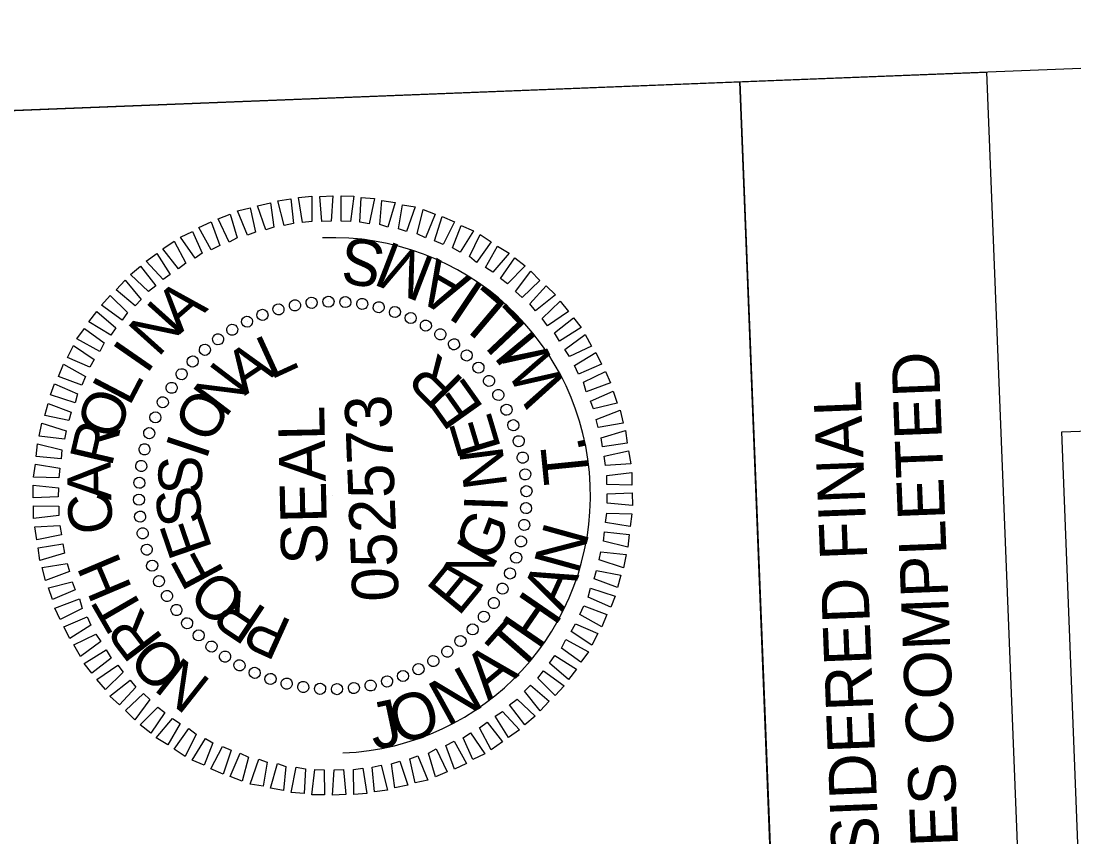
# Model space of a CAD drawing. Extents: x 1627905 to 1629071, y 761064 to 763101.
# Drawn here: x 1627988 to 1628124.3, y 762759.2 to 762864.8 of the extents above; entities that cross this region are included whole.
import ezdxf

# ---------------------------------------------------------------- set-up
doc = ezdxf.new("R2010")
doc.units = 0
for name, color, linetype in [('Prop DSN Text', 7, 'Continuous'), ('Scratch_Level_0', 7, 'Continuous'), ('Sheet Clip Boundary CELL', 7, 'Continuous'), ('Sheet Plan And Profile CELL', 7, 'Continuous'), ('Sheet Professional Seal CELL', 7, 'Continuous'), ('Sheet Profile Grid Minor CELL', 7, 'Continuous'), ('Sheet Sticker Exception Certification CELL', 7, 'Continuous')]:
    doc.layers.add(name, color=color, linetype=linetype)

msp = doc.modelspace()

# ---------------------------------------------------------------- linework, layer by layer
at = {"layer": 'Scratch_Level_0'}
msp.add_arc((1628028.37, 762803.44), 33.36, 272.2582, 92.2582, dxfattribs=at)
at = {"layer": 'Sheet Clip Boundary CELL'}
msp.add_lwpolyline([(1628129.05, 762651.6), (1628122.74, 762811.67), (1628982.18, 762845.56), (1629039.43, 761393.61), (1627990.25, 761352.23), (1627946.91, 762451.28), (1628013.55, 762453.91), (1628005.94, 762646.74)], close=True, dxfattribs=at)
at = {"layer": 'Sheet Plan And Profile CELL'}
for points in [[(1627931.14, 762851.07), (1627990.25, 761352.23), (1629039.43, 761393.61), (1628980.33, 762892.44)], [(1627972.6, 762752.63), (1627968.66, 762852.55), (1628081.08, 762856.98), (1628085.02, 762757.06)]]:
    msp.add_lwpolyline(points, close=True, dxfattribs=at)
at = {"layer": 'Sheet Professional Seal CELL'}
for p, q in [((1628021.32, 762827.53), (1628021.32, 762827.53)), ((1628023.5, 762828.02), (1628023.5, 762828.02)), ((1628025.64, 762828.4), (1628025.64, 762828.4)), ((1628027.83, 762828.54), (1628027.83, 762828.54)), ((1628030.04, 762828.47), (1628030.04, 762828.47)), ((1628032.2, 762828.21), (1628032.2, 762828.21)), ((1628034.32, 762827.84), (1628034.32, 762827.84)), ((1628019.24, 762826.85), (1628019.24, 762826.85)), ((1628036.44, 762827.23), (1628036.44, 762827.23)), ((1628038.48, 762826.4), (1628038.48, 762826.4)), ((1628015.37, 762824.89), (1628015.37, 762824.89)), ((1628017.28, 762825.97), (1628017.28, 762825.97)), ((1628040.46, 762825.48), (1628040.46, 762825.48)), ((1628013.52, 762823.67), (1628013.52, 762823.67)), ((1628042.31, 762824.3), (1628042.31, 762824.3)), ((1628011.82, 762822.35), (1628011.82, 762822.35)), ((1628044.11, 762823.02), (1628044.11, 762823.02)), ((1628010.23, 762820.79), (1628010.23, 762820.79)), ((1628045.72, 762821.59), (1628045.72, 762821.59)), ((1628047.29, 762820), (1628047.29, 762820)), ((1628008.79, 762819.18), (1628008.79, 762819.18)), ((1628048.6, 762818.3), (1628048.6, 762818.3)), ((1628007.51, 762817.38), (1628007.51, 762817.38)), ((1628006.33, 762815.53), (1628006.33, 762815.53)), ((1628049.83, 762816.44), (1628049.83, 762816.44)), ((1628050.9, 762814.54), (1628050.9, 762814.54)), ((1628005.41, 762813.54), (1628005.41, 762813.54)), ((1628051.78, 762812.57), (1628051.78, 762812.57)), ((1628004.59, 762811.51), (1628004.59, 762811.51)), ((1628052.46, 762810.49), (1628052.46, 762810.49)), ((1628003.97, 762809.38), (1628003.97, 762809.38)), ((1628052.95, 762808.31), (1628052.95, 762808.31)), ((1628003.6, 762807.27), (1628003.6, 762807.27)), ((1628053.34, 762806.17), (1628053.34, 762806.17)), ((1628003.34, 762805.1), (1628003.34, 762805.1)), ((1628003.28, 762802.9), (1628003.28, 762802.9)), ((1628028.37, 762803.44), (1628028.37, 762803.44)), ((1628053.47, 762803.98), (1628053.47, 762803.98)), ((1628053.41, 762801.77), (1628053.41, 762801.77)), ((1628003.41, 762800.7), (1628003.41, 762800.7)), ((1628053.14, 762799.61), (1628053.14, 762799.61)), ((1628003.8, 762798.57), (1628003.8, 762798.57)), ((1628052.78, 762797.5), (1628052.78, 762797.5)), ((1628004.28, 762796.38), (1628004.28, 762796.38)), ((1628052.16, 762795.37), (1628052.16, 762795.37)), ((1628004.97, 762794.31), (1628004.97, 762794.31)), ((1628051.34, 762793.34), (1628051.34, 762793.34)), ((1628005.84, 762792.34), (1628005.84, 762792.34)), ((1628050.42, 762791.35), (1628050.42, 762791.35)), ((1628006.92, 762790.43), (1628006.92, 762790.43)), ((1628049.24, 762789.5), (1628049.24, 762789.5)), ((1628008.14, 762788.58), (1628008.14, 762788.58)), ((1628009.46, 762786.88), (1628009.46, 762786.88)), ((1628047.96, 762787.7), (1628047.96, 762787.7)), ((1628011.03, 762785.29), (1628011.03, 762785.29)), ((1628046.52, 762786.09), (1628046.52, 762786.09)), ((1628012.63, 762783.85), (1628012.63, 762783.85)), ((1628044.93, 762784.53), (1628044.93, 762784.53)), ((1628014.44, 762782.57), (1628014.44, 762782.57)), ((1628043.23, 762783.21), (1628043.23, 762783.21)), ((1628016.28, 762781.4), (1628016.28, 762781.4)), ((1628041.38, 762781.98), (1628041.38, 762781.98)), ((1628018.27, 762780.47), (1628018.27, 762780.47)), ((1628037.5, 762780.03), (1628037.5, 762780.03)), ((1628039.47, 762780.91), (1628039.47, 762780.91)), ((1628020.3, 762779.65), (1628020.3, 762779.65)), ((1628022.43, 762779.04), (1628022.43, 762779.04)), ((1628024.55, 762778.67), (1628024.55, 762778.67)), ((1628026.71, 762778.4), (1628026.71, 762778.4)), ((1628028.91, 762778.34), (1628028.91, 762778.34)), ((1628031.11, 762778.48), (1628031.11, 762778.48)), ((1628033.25, 762778.86), (1628033.25, 762778.86)), ((1628035.43, 762779.35), (1628035.43, 762779.35))]:
    msp.add_line(p, q, dxfattribs=at)
for points in [[(1628019.71, 762837.82), (1628018.64, 762840.93), (1628020.33, 762841.3), (1628020.75, 762838.17)], [(1628022.09, 762838.37), (1628021.27, 762841.59), (1628022.96, 762841.81), (1628023.28, 762838.62)], [(1628024.48, 762838.76), (1628023.95, 762841.99), (1628025.65, 762842.16), (1628025.67, 762838.91)], [(1628026.98, 762838.91), (1628026.7, 762842.15), (1628028.4, 762842.22), (1628028.17, 762838.96)], [(1628029.48, 762838.96), (1628029.45, 762842.21), (1628031.1, 762842.18), (1628030.68, 762838.91)], [(1628031.88, 762838.8), (1628032.06, 762842.01), (1628033.76, 762841.88), (1628033.09, 762838.6)], [(1628034.45, 762838.51), (1628034.72, 762841.62), (1628036.44, 762841.34), (1628035.51, 762838.15)], [(1628036.87, 762837.95), (1628037.4, 762841.07), (1628039.06, 762840.79), (1628037.94, 762837.59)], [(1628014.97, 762836.24), (1628013.55, 762839.23), (1628015.08, 762839.84), (1628016, 762836.78)], [(1628017.34, 762837.13), (1628016.06, 762840.28), (1628017.7, 762840.65), (1628018.37, 762837.52)], [(1628039.3, 762837.3), (1628040.08, 762840.43), (1628041.65, 762839.84), (1628040.37, 762836.79)], [(1628012.66, 762835.24), (1628011.04, 762838.13), (1628012.62, 762838.85), (1628013.74, 762835.79)], [(1628041.54, 762836.38), (1628042.56, 762839.53), (1628044.14, 762838.84), (1628042.65, 762835.93)], [(1628043.87, 762835.47), (1628045.01, 762838.37), (1628046.59, 762837.68), (1628044.85, 762834.91)], [(1628010.55, 762834.16), (1628008.69, 762836.89), (1628010.21, 762837.6), (1628011.48, 762834.8)], [(1628046.07, 762834.36), (1628047.46, 762837.22), (1628048.9, 762836.27), (1628047, 762833.6)], [(1628008.4, 762832.77), (1628006.4, 762835.35), (1628007.86, 762836.36), (1628009.37, 762833.51)], [(1628048.13, 762832.94), (1628049.72, 762835.71), (1628051.21, 762834.81), (1628049.1, 762832.33)], [(1628006.41, 762831.4), (1628004.21, 762833.76), (1628005.62, 762834.77), (1628007.33, 762832.03)], [(1628050.08, 762831.52), (1628051.93, 762834.19), (1628053.27, 762833.14), (1628051.01, 762830.85)], [(1628004.52, 762829.82), (1628002.18, 762832.03), (1628003.48, 762833.13), (1628005.49, 762830.56)], [(1628052.05, 762829.84), (1628054, 762832.47), (1628055.2, 762831.27), (1628052.88, 762829.07)], [(1628002.79, 762828), (1628000.35, 762830.06), (1628001.51, 762831.3), (1628003.56, 762828.78)], [(1628053.87, 762828.26), (1628055.98, 762830.55), (1628057.22, 762829.4), (1628054.6, 762827.34)], [(1628001.11, 762826.13), (1627998.43, 762828.08), (1627999.58, 762829.32), (1628001.82, 762827.11)], [(1628055.49, 762826.33), (1628057.81, 762828.57), (1628058.91, 762827.26), (1628056.18, 762825.4)], [(1627999.63, 762824.17), (1627996.81, 762825.91), (1627997.86, 762827.26), (1628000.3, 762825.15)], [(1628057.07, 762824.49), (1628059.54, 762826.43), (1628060.54, 762825.17), (1628057.71, 762823.41)], [(1627998.22, 762822.07), (1627995.25, 762823.7), (1627996.25, 762825.04), (1627998.77, 762823.19)], [(1628058.4, 762822.34), (1628061.03, 762824.29), (1628061.89, 762822.77), (1628059.04, 762821.41)], [(1627996.94, 762820.06), (1627994.04, 762821.3), (1627994.83, 762822.83), (1627997.51, 762821.04)], [(1628059.69, 762820.24), (1628062.42, 762821.94), (1628063.18, 762820.42), (1628060.18, 762819.15)], [(1627995.89, 762817.72), (1627992.89, 762818.85), (1627993.53, 762820.43), (1627996.39, 762818.84)], [(1628060.82, 762818.08), (1628063.67, 762819.49), (1628064.33, 762818.02), (1628061.17, 762816.84)], [(1627995.03, 762815.43), (1627991.83, 762816.46), (1627992.38, 762817.88), (1627995.33, 762816.6)], [(1628061.72, 762815.66), (1628064.67, 762816.93), (1628065.18, 762815.4), (1628062.11, 762814.63)], [(1627994.21, 762813.15), (1627991.09, 762813.78), (1627991.53, 762815.35), (1627994.52, 762814.21)], [(1628062.46, 762813.29), (1628065.57, 762814.46), (1628065.99, 762812.78), (1628062.75, 762812.25)], [(1627993.66, 762810.73), (1627990.39, 762811.1), (1627990.73, 762812.81), (1627993.87, 762811.79)], [(1628063.11, 762810.91), (1628066.27, 762811.84), (1628066.49, 762810.2), (1628063.3, 762809.72)], [(1627993.21, 762808.16), (1627990, 762808.48), (1627990.18, 762810.14), (1627993.31, 762809.36)], [(1628063.5, 762808.53), (1628066.68, 762809.2), (1628066.94, 762807.51), (1628063.7, 762807.33)], [(1627992.91, 762805.74), (1627989.65, 762805.82), (1627989.88, 762807.48), (1627993.06, 762806.95)], [(1628063.85, 762806.04), (1628067.09, 762806.42), (1628067.1, 762804.77), (1628063.85, 762804.84)], [(1627992.85, 762803.24), (1627989.61, 762803.11), (1627989.59, 762804.76), (1627992.86, 762804.44)], [(1628063.89, 762803.64), (1628067.14, 762803.77), (1628067.16, 762802.12), (1628063.89, 762802.44)], [(1627992.9, 762800.84), (1627989.66, 762800.46), (1627989.65, 762802.11), (1627992.9, 762802.04)], [(1628063.84, 762801.13), (1628067.1, 762801.06), (1628066.86, 762799.4), (1628063.69, 762799.93)], [(1627993.25, 762798.35), (1627990.07, 762797.68), (1627989.8, 762799.37), (1627993.05, 762799.54)], [(1628063.54, 762798.72), (1628066.75, 762798.4), (1628066.57, 762796.74), (1628063.43, 762797.52)], [(1627993.64, 762795.96), (1627990.48, 762795.04), (1627990.26, 762796.68), (1627993.44, 762797.16)], [(1628063.09, 762796.15), (1628066.36, 762795.78), (1628066.02, 762794.07), (1628062.88, 762795.09)], [(1627994.29, 762793.59), (1627991.18, 762792.41), (1627990.76, 762794.1), (1627993.99, 762794.63)], [(1628062.53, 762793.73), (1628065.66, 762793.1), (1628065.22, 762791.53), (1628062.22, 762792.66)], [(1627995.03, 762791.22), (1627992.08, 762789.95), (1627991.57, 762791.48), (1627994.64, 762792.25)], [(1628061.72, 762791.44), (1628064.92, 762790.42), (1628064.37, 762789), (1628061.42, 762790.28)], [(1627995.93, 762788.8), (1627993.08, 762787.39), (1627992.42, 762788.86), (1627995.58, 762790.04)], [(1628060.86, 762789.16), (1628063.86, 762788.03), (1628063.22, 762786.45), (1628060.36, 762788.04)], [(1627997.06, 762786.64), (1627994.33, 762784.93), (1627993.57, 762786.45), (1627996.57, 762787.72)], [(1628059.8, 762786.81), (1628062.7, 762785.58), (1628061.91, 762784.05), (1628059.24, 762785.84)], [(1627998.35, 762784.54), (1627995.72, 762782.59), (1627994.86, 762784.1), (1627997.71, 762785.47)], [(1628058.53, 762784.81), (1628061.5, 762783.18), (1628060.5, 762781.84), (1628057.98, 762783.69)], [(1627999.68, 762782.39), (1627997.21, 762780.44), (1627996.21, 762781.7), (1627999.04, 762783.47)], [(1628057.11, 762782.71), (1628059.93, 762780.97), (1628058.89, 762779.62), (1628056.45, 762781.73)], [(1628001.25, 762780.55), (1627998.94, 762778.31), (1627997.84, 762779.62), (1628000.57, 762781.48)], [(1628055.64, 762780.75), (1628058.32, 762778.8), (1628057.17, 762777.55), (1628054.93, 762779.77)], [(1628002.88, 762778.62), (1628000.77, 762776.33), (1627999.52, 762777.48), (1628002.15, 762779.54)], [(1628053.96, 762778.88), (1628056.39, 762776.82), (1628055.24, 762775.58), (1628053.19, 762778.1)], [(1628004.7, 762777.04), (1628002.75, 762774.41), (1628001.55, 762775.61), (1628003.86, 762777.8)], [(1628052.23, 762777.06), (1628054.57, 762774.85), (1628053.26, 762773.75), (1628051.26, 762776.32)], [(1628006.66, 762775.36), (1628004.82, 762772.69), (1628003.47, 762773.73), (1628005.74, 762776.03)], [(1628008.62, 762773.94), (1628007.03, 762771.17), (1628005.54, 762772.07), (1628007.65, 762774.55)], [(1628050.34, 762775.48), (1628052.54, 762773.12), (1628051.13, 762772.11), (1628049.42, 762774.85)], [(1628010.68, 762772.52), (1628009.29, 762769.66), (1628007.85, 762770.6), (1628009.75, 762773.28)], [(1628048.35, 762774.1), (1628050.35, 762771.53), (1628048.89, 762770.52), (1628047.37, 762773.36)], [(1628012.87, 762771.4), (1628011.74, 762768.51), (1628010.16, 762769.19), (1628011.9, 762771.97)], [(1628044.09, 762771.63), (1628045.7, 762768.74), (1628044.13, 762768.03), (1628043.01, 762771.09)], [(1628046.2, 762772.72), (1628048.06, 762769.99), (1628046.53, 762769.28), (1628045.27, 762772.08)], [(1628015.21, 762770.49), (1628014.18, 762767.35), (1628012.61, 762768.04), (1628014.09, 762770.95)], [(1628041.78, 762770.64), (1628043.2, 762767.65), (1628041.67, 762767.03), (1628040.75, 762770.1)], [(1628017.45, 762769.58), (1628016.67, 762766.45), (1628015.1, 762767.04), (1628016.38, 762770.09)], [(1628019.88, 762768.93), (1628019.35, 762765.8), (1628017.69, 762766.09), (1628018.81, 762769.29)], [(1628037.04, 762769.05), (1628038.11, 762765.94), (1628036.42, 762765.58), (1628036, 762768.71)], [(1628039.41, 762769.75), (1628040.69, 762766.6), (1628039.05, 762766.23), (1628038.37, 762769.36)], [(1628022.3, 762768.37), (1628022.02, 762765.26), (1628020.31, 762765.54), (1628021.24, 762768.73)], [(1628024.86, 762768.07), (1628024.69, 762764.86), (1628022.98, 762765), (1628023.66, 762768.28)], [(1628027.27, 762767.92), (1628027.3, 762764.67), (1628025.65, 762764.7), (1628026.07, 762767.97)], [(1628029.77, 762767.97), (1628030.05, 762764.73), (1628028.35, 762764.66), (1628028.57, 762767.92)], [(1628032.27, 762768.12), (1628032.8, 762764.88), (1628031.1, 762764.72), (1628031.07, 762767.97)], [(1628034.66, 762768.51), (1628035.48, 762765.29), (1628033.79, 762765.07), (1628033.46, 762768.26)]]:
    msp.add_lwpolyline(points, close=True, dxfattribs=at)
for centre, major_axis in [((1628023.48, 762828.04), (-0.141, 0.706)), ((1628025.64, 762828.37), (-0.078, 0.716)), ((1628027.82, 762828.51), (-0.016, 0.72)), ((1628030.01, 762828.47), (0.047, 0.718)), ((1628032.19, 762828.23), (0.109, 0.712)), ((1628019.28, 762826.81), (-0.261, 0.671)), ((1628021.35, 762827.52), (-0.202, 0.691)), ((1628034.33, 762827.8), (0.171, 0.699)), ((1628036.43, 762827.19), (0.231, 0.682)), ((1628017.28, 762825.93), (-0.319, 0.646)), ((1628038.47, 762826.4), (0.29, 0.659)), ((1628040.43, 762825.43), (0.346, 0.631)), ((1628015.36, 762824.88), (-0.374, 0.615)), ((1628042.3, 762824.29), (0.4, 0.599)), ((1628013.54, 762823.66), (-0.426, 0.581)), ((1628044.07, 762823), (0.451, 0.562)), ((1628011.83, 762822.29), (-0.475, 0.541)), ((1628045.71, 762821.56), (0.498, 0.52)), ((1628010.25, 762820.78), (-0.52, 0.498)), ((1628047.23, 762819.98), (0.541, 0.475)), ((1628008.81, 762819.13), (-0.562, 0.451)), ((1628007.52, 762817.37), (-0.599, 0.4)), ((1628048.6, 762818.27), (0.581, 0.426)), ((1628049.81, 762816.45), (0.615, 0.374)), ((1628006.38, 762815.5), (-0.631, 0.346)), ((1628050.87, 762814.53), (0.646, 0.319)), ((1628005.42, 762813.54), (-0.659, 0.29)), ((1628051.75, 762812.53), (0.671, 0.261)), ((1628004.62, 762811.5), (-0.682, 0.231)), ((1628052.45, 762810.46), (0.691, 0.202)), ((1628004.01, 762809.4), (-0.699, 0.171)), ((1628052.97, 762808.34), (0.706, 0.141)), ((1628003.59, 762807.25), (-0.712, 0.109)), ((1628053.3, 762806.17), (0.716, 0.078)), ((1628003.35, 762805.08), (-0.718, 0.047)), ((1628053.45, 762803.99), (0.72, 0.016)), ((1628003.3, 762802.89), (-0.72, -0.016)), ((1628053.4, 762801.8), (0.718, -0.047)), ((1628003.44, 762800.71), (-0.716, -0.078)), ((1628053.16, 762799.63), (0.712, -0.109)), ((1628003.78, 762798.54), (-0.706, -0.141)), ((1628052.74, 762797.48), (0.699, -0.171)), ((1628004.3, 762796.42), (-0.691, -0.202)), ((1628052.12, 762795.38), (0.682, -0.231)), ((1628005, 762794.35), (-0.671, -0.261)), ((1628051.33, 762793.34), (0.659, -0.29)), ((1628005.88, 762792.34), (-0.646, -0.319)), ((1628050.36, 762791.38), (0.631, -0.346)), ((1628006.93, 762790.43), (-0.615, -0.374)), ((1628008.15, 762788.61), (-0.581, -0.426)), ((1628049.23, 762789.51), (0.599, -0.4)), ((1628047.94, 762787.74), (0.562, -0.451)), ((1628009.52, 762786.9), (-0.541, -0.475)), ((1628046.49, 762786.1), (0.52, -0.498)), ((1628011.03, 762785.32), (-0.498, -0.52)), ((1628044.91, 762784.59), (0.475, -0.541)), ((1628012.68, 762783.88), (-0.451, -0.562)), ((1628043.21, 762783.22), (0.426, -0.581)), ((1628014.44, 762782.58), (-0.4, -0.599)), ((1628041.39, 762782), (0.374, -0.615)), ((1628016.31, 762781.45), (-0.346, -0.631)), ((1628018.28, 762780.48), (-0.29, -0.659)), ((1628039.47, 762780.95), (0.319, -0.646)), ((1628020.32, 762779.69), (-0.231, -0.682)), ((1628022.42, 762779.08), (-0.171, -0.699)), ((1628035.4, 762779.36), (0.202, -0.691)), ((1628037.47, 762780.07), (0.261, -0.671)), ((1628024.56, 762778.65), (-0.109, -0.712)), ((1628026.74, 762778.41), (-0.047, -0.718)), ((1628028.92, 762778.37), (0.016, -0.72)), ((1628031.11, 762778.51), (0.078, -0.716)), ((1628033.27, 762778.84), (0.141, -0.706))]:
    msp.add_ellipse(centre, major_axis=major_axis, ratio=0.999708, dxfattribs=at)
at = {"layer": 'Sheet Sticker Exception Certification CELL'}
for p, q in [((1628081.08, 762856.98), (1628113.03, 762858.24)), ((1628113.01, 762858.24), (1628120.9, 762658.35)), ((1628088.94, 762657.09), (1628081.06, 762856.98))]:
    msp.add_line(p, q, dxfattribs=at)

# ---------------------------------------------------------------- texts
at = {"layer": 'Prop DSN Text'}
for s, rotation, p in [('S', 170.5234, (1628035.39, 762836.09)), ('M', 158.8769, (1628041.84, 762834)), ('A', 149.947, (1628046.42, 762831.54)), ('I', 146.1065, (1628048.26, 762830.27)), ('L', 139.7681, (1628051.1, 762827.91)), ('L', 133.4297, (1628053.67, 762825.25)), ('I', 129.5892, (1628055.07, 762823.51)), ('W', 116.928, (1628058.82, 762817.17)), ('.', 102.5495, (1628061.28, 762809.18)), ('T', 95.6803, (1628061.73, 762805.2)), ('N', 74.5419, (1628060.12, 762793.06)), ('A', 65.6119, (1628058.12, 762788.25)), ('H', 55.5267, (1628055, 762783.28)), ('T', 48.6575, (1628052.4, 762780.24)), ('A', 39.7275, (1628048.51, 762776.79)), ('N', 28.8929, (1628043.14, 762773.48)), ('J', 11.9042, (1628033.74, 762770.47)), ('O', 17.2153, (1628036.77, 762771.11))]:
    msp.add_text(s, height=6, rotation=rotation, dxfattribs=at).set_placement(p)
at = {"layer": 'Sheet Professional Seal CELL'}
for s, height, rotation, p in [('A', 5.64, 40.8753, (1628008.59, 762824.28)), ('N', 5.64, 48.0771, (1628005.76, 762821.21)), ('I', 5.64, 55.2783, (1628004.29, 762819)), ('L', 5.64, 24.659, (1628020.33, 762818.38)), ('A', 5.64, 34.0185, (1628016.96, 762816.3)), ('N', 5.64, 52.7348, (1628014.47, 762813.35)), ('R', 5.64, 134.7396, (1628045.55, 762818.23)), ('L', 5.64, 62.4791, (1628002.05, 762814.86)), ('E', 5.64, 125.3823, (1628048.04, 762814.77)), ('O', 5.64, 69.6794, (1628000.38, 762810.39)), ('O', 5.64, 62.0917, (1628012.61, 762809.92)), ('SEAL', 5.998, 91.2582, (1628027.72, 762794.56)), ('E', 5.64, 106.67, (1628050.2, 762809.55)), ('R', 5.64, 76.8793, (1627999.76, 762807.01)), ('I', 5.64, 71.4478, (1628011.99, 762807.9)), ('N', 5.64, 97.3146, (1628050.99, 762804.63)), ('A', 5.64, 91.2785, (1627999.73, 762802.81)), ('S', 5.64, 90.1586, (1628011.46, 762803.57)), ('S', 5.64, 99.5138, (1628011.65, 762799.98)), ('C', 5.64, 98.4781, (1628000.18, 762798.87)), ('I', 5.64, 87.9594, (1628050.98, 762801.28)), ('E', 5.64, 108.8693, (1628012.83, 762796.57)), ('G', 5.64, 69.2484, (1628049.34, 762794.66)), ('N', 5.64, 59.8921, (1628047.24, 762790.77)), ('F', 5.64, 118.2252, (1628014.46, 762793.43)), ('H', 5.64, 112.8777, (1628002.48, 762791.36)), ('E', 5.64, 50.5351, (1628044.66, 762787.67)), ('O', 5.64, 136.9394, (1628017.54, 762790.25)), ('R', 5.64, 146.2978, (1628020.05, 762788.6)), ('T', 5.64, 120.078, (1628004.26, 762788.18)), ('R', 5.64, 127.2787, (1628006.59, 762784.87)), ('P', 5.64, 155.6571, (1628023.31, 762787.13)), ('O', 5.64, 134.4799, (1628009.82, 762781.54)), ('N', 5.64, 141.6817, (1628012.81, 762779.36))]:
    msp.add_text(s, height=height, rotation=rotation, dxfattribs=at).set_placement(p)
at = {"layer": 'Sheet Profile Grid Minor CELL'}
msp.add_text('052573', height=5.998, rotation=92.2582, dxfattribs=at).set_placement((1628036.93, 762789.81))
at = {"layer": 'Sheet Sticker Exception Certification CELL'}
for s, p in [('UNLESS ALL SIGNATURES COMPLETED', (1628113.03, 762663.93)), ('DOCUMENT NOT CONSIDERED FINAL', (1628102.55, 762669.26))]:
    msp.add_text(s, height=6.124, rotation=92.2582, dxfattribs=at).set_placement(p)

doc.saveas('drawing.dxf')
